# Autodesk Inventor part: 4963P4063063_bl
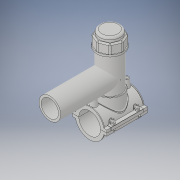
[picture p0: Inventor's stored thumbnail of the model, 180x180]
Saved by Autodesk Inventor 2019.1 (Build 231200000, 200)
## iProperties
Created: 2017-07
Part Number: 4963P4063063_bl
Material: Generic
Document SubType Name: Modeling
Designer: KIM
Density: 1 g/cm^3
Appearance: Default
Author: KIM
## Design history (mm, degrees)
derived "4963P4.ipt"
feature "Solid1::4963P4.ipt" dims "ScaleForDerivedMember" = 10
feature "Solid2::4963P4.ipt" dims "ScaleForDerivedMember" = 10
feature "Solid3::4963P4.ipt" dims "ScaleForDerivedMember" = 10
tag "TaggingFeature1"
body "Solid1"
body "Solid2"
body "Solid3"
other parameters: "d0" = 63 [user parameter], "d3" = 15.75 [user parameter], "d4" = 118 [user parameter], "d5" = 0 [user parameter], "d6" = 0.1 [user parameter], "d8" = 0 [user parameter], "d19" = 6 [user parameter], "d20" = 6 [user parameter], "d21" = 70.8 [user parameter], "d23" = 0 [user parameter], "d24" = 35.4 [user parameter], "d26" = 0 [user parameter], "d27" = 3 [user parameter], "d28" = 3 [user parameter], "d29" = 3 [user parameter], "d30" = 21 [user parameter], "d31" = 6 [user parameter], "d32" = 0 [user parameter], "d33" = 0 [user parameter], "d34" = 0.6 [user parameter], "d40" = 42.588 [user parameter], "d41" = 75.6 [user parameter], "d43" = 0 [user parameter], "d45" = 0 [user parameter], "d47" = 111.75 [user parameter], "d70" = 15 [user parameter], "d72" = 0 [user parameter], "d73" = 6 [user parameter], "d75" = 5 [user parameter], "d76" = 0 [user parameter], "d77" = 3.15 [user parameter], "d78" = 61.5 [user parameter], "d79" = 15 [user parameter], "d80" = 47.2 [user parameter], "d82" = 5 deg [user parameter], "d84" = 4 [user parameter], "d85" = 14 [user parameter], "d86" = 0 [user parameter], "d87" = 3 [user parameter], "d88" = 0 [user parameter], "d89" = 1 [user parameter], "d90" = 1 [user parameter], "d91" = 94.4 [user parameter], "d92" = 0 [user parameter], "d93" = 0.5 [user parameter], "d94" = 33.15789 [user parameter], "d96" = 83.538 [user parameter], "d97" = 2.36 [user parameter], "d98" = 0 [user parameter], "d102" = 0.63 [user parameter], "d120" = 140 deg [user parameter], "d121" = 24.228 [user parameter], "d122" = 20 deg [user parameter], "d123" = 163.8 [user parameter], "d124" = 49.14 [user parameter], "d126" = 0 [user parameter], "d143" = 64.89 [user parameter], "d145" = 14.53846 [user parameter], "d149" = 0.945 [user parameter], "d150" = 15.99231 [user parameter], "d153" = 118 [user parameter], "d154" = 0 [user parameter], "d156" = 40.95 [user parameter], "d157" = 160 deg [user parameter], "d159" = 3.78 [user parameter], "d161" = 0.945 [user parameter], "d162" = 70.8 [user parameter], "d163" = 0 [user parameter], "d164" = 31.5 [user parameter], "d167" = 6.3 [user parameter], "d168" = 39.95122 [user parameter], "d170" = 3.75 [user parameter], "d172" = 0 [user parameter], "d173" = 1 [user parameter], "d175" = 31.5 [user parameter], "d176" = 20 deg [user parameter], "d177" = 4.41 [user parameter], "d178" = 18.9 [user parameter], "d180" = 0 [user parameter], "d183" = 7.56 [user parameter], "d184" = 3.528 [user parameter], "d185" = 38.35 [user parameter], "d186" = 38.35 [user parameter], "d187" = 40.95 [user parameter], "d188" = 5.67 [user parameter], "d189" = 4.41 [user parameter], "d190" = 0 [user parameter], "d191" = 61.425 [user parameter], "d193" = 8 [user parameter], "d194" = 4.13 [user parameter], "d195" = 90 deg [user parameter], "d197" = 0 [user parameter], "d199" = 0 [user parameter], "d200" = 9.45 [user parameter], "d202" = 0 [user parameter], "d203" = 177 [user parameter], "d204" = 71.82 [user parameter], "d205" = 52.92 [user parameter], "d206" = 64.26 [user parameter], "d207" = 132.75 [user parameter], "d208" = 138.06 [user parameter], "d209" = 164.61 [user parameter], "d210" = 65.016 [user parameter], "d211" = 75.6 [user parameter], "d212" = 60.48 [user parameter], "d213" = 29.25 [user parameter], "d216" = 0 [user parameter], "d217" = 6.3 [user parameter], "d218" = 6.3 [user parameter], "d219" = 1.26 [user parameter], "d222" = 63 [user parameter], "d224" = 0 [user parameter], "d225" = 64 [user parameter], "d226" = 63 [user parameter], "d227" = 50.4 [user parameter], "d228" = 175 [user parameter], "d230" = 3.78 [user parameter], "d_" = 63 [user parameter], "L_" = 118 [user parameter], "d_t" = 6 [user parameter]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
